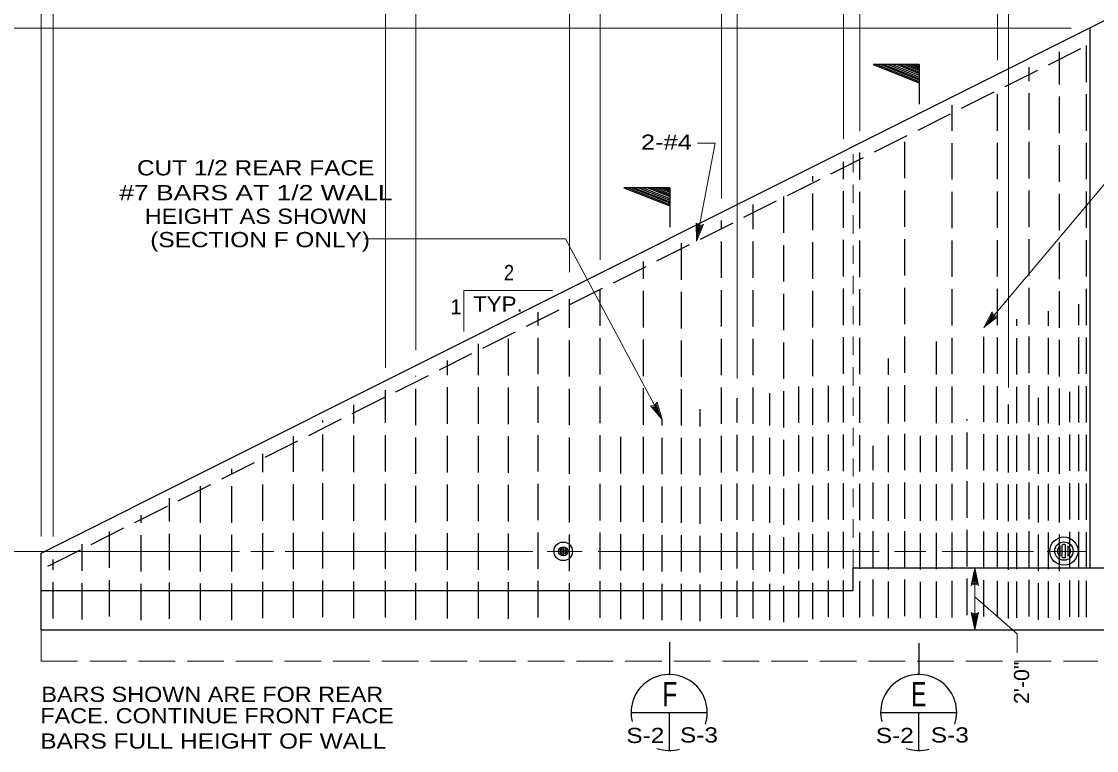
# Model space of a CAD drawing. Extents: x -22.3 to 19.7, y -11.8 to 18.2.
# Drawn here: x -17.19 to -8.36, y 7.76 to 13.75 of the extents above; entities that cross this region are included whole.
import ezdxf
from ezdxf.enums import TextEntityAlignment as Align

# ---------------------------------------------------------------- set-up
doc = ezdxf.new("R2010")
doc.units = 0
doc.header["$LTSCALE"] = 0.05
doc.linetypes.add('LONG_DASHED', pattern=[7.5, 6, -1.5])
doc.linetypes.add('MEDIUM_DASHED', pattern=[4.5, 3, -1.5])
doc.layers.add('1', color=7, linetype='Continuous', lineweight=13)
doc.layers.add('2', color=7, linetype='Continuous', lineweight=13)

msp = doc.modelspace()

# ---------------------------------------------------------------- linework, layer by layer
at = {"layer": '1'}
for p, q in [((-17.03142, 9.51631), (-17.03142, 15.50531)), ((-16.93242, 9.51631), (-16.93242, 15.50531)), ((-10.43842, 12.78231), (-10.43842, 15.50531)), ((-10.30342, 12.84831), (-10.30342, 15.50531)), ((-14.20242, 10.90131), (-14.20242, 14.77631)), ((-13.95142, 11.04731), (-13.95142, 14.77631)), ((-12.68842, 11.68931), (-12.68842, 14.77631)), ((-12.43842, 11.79131), (-12.43842, 14.77631)), ((-11.43942, 12.29431), (-11.43942, 14.77631)), ((-11.31242, 10.81431), (-11.31242, 14.77631)), ((-9.17242, 13.43131), (-9.17242, 14.77631)), ((-9.08142, 10.74131), (-9.08142, 14.77631)), ((-8.56742, 13.69631), (-18.54542, 13.69631)), ((-11.64642, 11.94431), (-11.64942, 12.09131)), ((-11.64642, 11.94431), (-11.58842, 12.08031)), ((-11.63942, 11.98031), (-11.64142, 12.07631)), ((-11.64142, 12.07631), (-11.62342, 12.06431)), ((-11.63942, 11.98031), (-11.60242, 12.06931)), ((-11.63242, 12.01631), (-11.63442, 12.06231)), ((-11.63442, 12.06231), (-11.62442, 12.05631)), ((-11.63242, 12.01631), (-11.61542, 12.05831)), ((-11.62442, 12.05631), (-11.61542, 12.05831)), ((-11.62342, 12.06431), (-11.60242, 12.06931)), ((-9.28542, 11.23331), (-9.21642, 11.36331)), ((-9.28542, 11.23331), (-9.16942, 11.32331)), ((-9.26142, 11.26131), (-9.21642, 11.34631)), ((-9.26142, 11.26131), (-9.18542, 11.32031)), ((-9.23842, 11.28931), (-9.21742, 11.33031)), ((-9.23842, 11.28931), (-9.20242, 11.31831)), ((-9.21742, 11.33031), (-9.21242, 11.32031)), ((-9.21642, 11.34631), (-9.20742, 11.32631)), ((-9.21242, 11.32031), (-9.20242, 11.31831)), ((-9.20742, 11.32631), (-9.18542, 11.32031)), ((-11.98642, 10.58531), (-11.97342, 10.60231)), ((-11.94642, 10.51031), (-11.97342, 10.60231)), ((-11.92942, 10.47731), (-11.96942, 10.61931)), ((-11.92942, 10.47731), (-12.02442, 10.58931)), ((-12.00842, 10.58331), (-11.98642, 10.58531)), ((-11.94642, 10.51031), (-12.00842, 10.58331)), ((-11.99342, 10.57631), (-11.98342, 10.57831)), ((-11.96342, 10.54131), (-11.99342, 10.57631)), ((-11.98342, 10.57831), (-11.97742, 10.58531)), ((-11.96342, 10.54131), (-11.97742, 10.58531)), ((-18.92042, 9.39231), (-15.40142, 9.39231)), ((-15.30742, 9.39231), (-15.11942, 9.39231)), ((-15.02542, 9.39231), (-12.99042, 9.39231)), ((-12.87342, 9.39231), (-12.58642, 9.39231)), ((-12.45542, 9.39231), (-10.14442, 9.39231)), ((-10.01842, 9.39231), (-9.76042, 9.39231)), ((-9.62742, 9.39231), (-8.87542, 9.39231)), ((-8.76542, 9.39231), (-8.44442, 9.39231)), ((-9.35842, 9.25831), (-9.38942, 9.11431)), ((-9.35842, 9.22131), (-9.37842, 9.12731)), ((-9.35842, 8.74831), (-9.35842, 9.25831)), ((-9.35842, 9.25831), (-9.32742, 9.11431)), ((-9.35842, 9.22131), (-9.33842, 9.12731)), ((-9.35842, 9.13631), (-9.37842, 9.12731)), ((-9.35842, 9.18531), (-9.36742, 9.14031)), ((-9.35842, 9.14431), (-9.36742, 9.14031)), ((-9.35842, 9.18531), (-9.34842, 9.14031)), ((-9.34842, 9.14031), (-9.35842, 9.14431)), ((-9.33842, 9.12731), (-9.35842, 9.13631)), ((-9.35842, 9.01931), (-9.00842, 8.71431)), ((-9.35842, 8.74831), (-9.38942, 8.89231)), ((-9.35842, 8.78531), (-9.37842, 8.87931)), ((-9.37842, 8.87931), (-9.35842, 8.87031)), ((-9.35842, 8.82131), (-9.36842, 8.86631)), ((-9.36842, 8.86631), (-9.35842, 8.86231)), ((-9.35842, 8.74831), (-9.32742, 8.89231)), ((-9.35842, 8.78531), (-9.33842, 8.87931)), ((-9.35842, 8.87031), (-9.33842, 8.87931)), ((-9.35842, 8.82131), (-9.34942, 8.86631)), ((-9.35842, 8.86231), (-9.34942, 8.86631)), ((-9.01042, 8.71431), (-9.01042, 8.56031))]:
    msp.add_line(p, q, dxfattribs=at)
at = {"layer": '1', "lineweight": 25}
for p, q in [((-8.41042, 9.25831), (-8.41042, 13.69631)), ((-12.76042, 9.37431), (-12.76042, 9.41631)), ((-12.74942, 9.36731), (-12.74942, 9.42131)), ((-12.73542, 9.36731), (-12.73542, 9.42131)), ((-12.72342, 9.37431), (-12.72342, 9.41631)), ((-8.65842, 9.35331), (-8.65842, 9.43831)), ((-8.64042, 9.34431), (-8.64042, 9.44831)), ((-8.61342, 9.34331), (-8.61342, 9.44831)), ((-8.59142, 9.35331), (-8.59142, 9.43831)), ((-17.03142, 8.74831), (1.83058, 8.74831))]:
    msp.add_line(p, q, dxfattribs=at)
at = {"layer": '1', "linetype": 'LONG_DASHED', "lineweight": 25}
for p, q in [((-16.97742, 9.27231), (-8.48842, 13.52731)), ((-8.44242, 8.85231), (-8.44242, 13.58331)), ((-8.66242, 8.83231), (-8.66242, 13.50031)), ((-8.91342, 8.85931), (-8.91342, 13.37331)), ((-9.17242, 8.85231), (-9.17242, 13.23131)), ((-9.54542, 8.85031), (-9.54542, 13.06331)), ((-9.93442, 8.86131), (-9.93442, 12.85431)), ((-10.30342, 8.84931), (-10.30342, 12.67231)), ((-10.43842, 8.85431), (-10.43842, 12.59731)), ((-10.69042, 8.83531), (-10.69042, 12.47931)), ((-10.92842, 8.81131), (-10.92842, 12.38131)), ((-11.18142, 8.84231), (-11.18142, 12.24631)), ((-11.43942, 8.84231), (-11.43942, 12.11331)), ((-11.76842, 8.82731), (-11.76842, 11.93831)), ((-12.08142, 8.83531), (-12.08142, 11.77731)), ((-12.43842, 8.84831), (-12.43842, 11.58931)), ((-12.68842, 8.83131), (-12.68842, 11.46631)), ((-8.50442, 8.85431), (-8.50442, 11.42531)), ((-12.94642, 8.85031), (-12.94642, 11.36131)), ((-8.75442, 8.84831), (-8.75442, 11.36731)), ((-9.28542, 8.85831), (-9.28542, 11.23331)), ((-9.01242, 8.84731), (-9.01242, 11.30331)), ((-13.19042, 8.84031), (-13.19042, 11.21631)), ((-13.43842, 8.84331), (-13.43842, 11.09931)), ((-9.67442, 8.84731), (-9.67442, 11.11931)), ((-13.69242, 8.84331), (-13.69242, 10.96331)), ((-10.06742, 8.84531), (-10.06742, 10.97931)), ((-13.95142, 8.83131), (-13.95142, 10.83631)), ((-10.80542, 8.85031), (-10.80542, 10.77831)), ((-10.56142, 8.85531), (-10.56142, 10.83331)), ((-14.20242, 8.85031), (-14.20242, 10.71931)), ((-11.04442, 8.82831), (-11.04442, 10.69531)), ((-8.57842, 8.85531), (-8.57842, 10.70431)), ((-11.31242, 8.85231), (-11.31242, 10.65231)), ((-9.08142, 8.84231), (-9.08142, 10.60231)), ((-8.83642, 8.83231), (-8.83642, 10.65531)), ((-14.46142, 8.84531), (-14.46142, 10.59831)), ((-11.61542, 8.82131), (-11.61542, 10.56231)), ((-14.71642, 8.85331), (-14.71642, 10.47331)), ((-11.92942, 8.82831), (-11.92942, 10.47731)), ((-9.42142, 8.87031), (-9.42142, 10.48131)), ((-14.95642, 8.84731), (-14.95642, 10.34031)), ((-12.26742, 8.83531), (-12.26742, 10.35931)), ((-9.80642, 8.84431), (-9.80642, 10.35631)), ((-10.19342, 8.86131), (-10.19342, 10.26231)), ((-15.21042, 8.84431), (-15.21042, 10.19531)), ((-15.46342, 8.82931), (-15.46342, 10.07131)), ((-15.72142, 8.82931), (-15.72142, 9.93131)), ((-15.97542, 8.83931), (-15.97542, 9.83031)), ((-16.20842, 8.82831), (-16.20842, 9.69031)), ((-16.47042, 8.85831), (-16.47042, 9.56531)), ((-16.69342, 8.83331), (-16.69342, 9.45331)), ((-16.93242, 8.84131), (-16.93242, 9.32831))]:
    msp.add_line(p, q, dxfattribs=at)
at = {"layer": '1', "linetype": 'MEDIUM_DASHED'}
msp.add_line((-10.35942, 9.25831), (-10.35942, 12.72331), dxfattribs=at)
at = {"layer": '1', "linetype": 'LONG_DASHED'}
for p, q in [((-17.03142, 8.74831), (-17.03142, 8.49031)), ((-17.03142, 8.49031), (-8.34742, 8.49031))]:
    msp.add_line(p, q, dxfattribs=at)
at = {"layer": '1'}
for points in [[(-9.28542, 11.23331), (-6.31842, 14.76331), (-5.93842, 14.76331)], [(-11.64642, 11.94431), (-11.49142, 12.75031), (-11.63742, 12.75031)], [(-11.64942, 12.09131), (-11.62142, 12.07231), (-11.58842, 12.08031)], [(-11.92942, 10.47731), (-12.72242, 11.96431), (-14.37142, 11.96431)], [(-13.55742, 11.20231), (-13.55742, 11.53931), (-12.82942, 11.53931)], [(-9.21642, 11.36331), (-9.20142, 11.33331), (-9.16942, 11.32331)], [(-12.02442, 10.58931), (-11.99042, 10.59231), (-11.96942, 10.61931)], [(-9.32742, 9.11431), (-9.35842, 9.12831), (-9.38942, 9.11431)], [(-9.38942, 8.89231), (-9.35842, 8.87831), (-9.32742, 8.89231)]]:
    msp.add_lwpolyline(points, dxfattribs=at)
at = {"layer": '1', "lineweight": 25}
for points in [[(-17.03142, 8.74831), (-17.03142, 9.37931), (-8.17942, 13.81631), (-1.11242, 13.81631), (1.83058, 12.34331)], [(-17.03142, 9.07131), (-10.35942, 9.07131), (-10.35942, 9.25831), (1.04358, 9.25831), (1.04358, 9.08631)]]:
    msp.add_lwpolyline(points, dxfattribs=at)
for centre, radius in [((-12.74142, 9.39431), 0.07624), ((-8.62642, 9.39631), 0.11574), ((-8.62642, 9.39631), 0.07571), ((-12.74142, 9.39431), 0.03821)]:
    msp.add_circle(centre, radius, dxfattribs=at)
for centre, radius, start, end in [((-12.74142, 9.39431), 0.02802, 130.60129, 226.4688), ((-12.74142, 9.39431), 0.02802, 251.56505, 282.09476), ((-12.74142, 9.39431), 0.02802, 77.47119, 106.50436), ((-12.74142, 9.39431), 0.02802, 310.60129, 50.71059), ((-8.62642, 9.39631), 0.05401, 126.02737, 233.1301), ((-8.62642, 9.39631), 0.05401, 75.96376, 104.03624), ((-8.62642, 9.39631), 0.05401, 309.80557, 48.81408), ((-8.62642, 9.39631), 0.05401, 254.93151, 282.75753)]:
    msp.add_arc(centre, radius, start, end, dxfattribs=at)
at = {"layer": '2', "lineweight": 25}
for p, q in [((-10.16342, 13.39531), (-9.81542, 13.25731)), ((-10.13042, 13.39531), (-9.81542, 13.27031)), ((-10.10742, 13.39531), (-9.81542, 13.27931)), ((-10.07142, 13.39531), (-9.81542, 13.29331)), ((-10.03742, 13.39531), (-9.81542, 13.30731)), ((-9.99642, 13.39531), (-9.81542, 13.32331)), ((-9.96942, 13.39531), (-9.81542, 13.33431)), ((-9.93742, 13.39531), (-9.81542, 13.34631)), ((-9.90842, 13.39531), (-9.81542, 13.35831)), ((-9.87942, 13.39531), (-9.81542, 13.36931)), ((-9.85942, 13.39531), (-9.81542, 13.37731)), ((-9.83242, 13.39531), (-9.81542, 13.38831)), ((-9.81542, 13.39531), (-9.81542, 13.07131)), ((-12.21342, 12.38331), (-11.86542, 12.24531)), ((-12.18042, 12.38331), (-11.86542, 12.25831)), ((-12.15742, 12.38331), (-11.86542, 12.26731)), ((-12.12142, 12.38331), (-11.86542, 12.28131)), ((-12.08742, 12.38331), (-11.86542, 12.29531)), ((-12.04642, 12.38331), (-11.86542, 12.31131)), ((-12.01942, 12.38331), (-11.86542, 12.32231)), ((-11.98742, 12.38331), (-11.86542, 12.33431)), ((-11.95842, 12.38331), (-11.86542, 12.34631)), ((-11.92942, 12.38331), (-11.86542, 12.35731)), ((-11.90942, 12.38331), (-11.86542, 12.36531)), ((-11.88242, 12.38331), (-11.86542, 12.37631)), ((-11.86542, 12.38331), (-11.86542, 12.05931)), ((-11.86542, 8.38331), (-11.86542, 8.64831)), ((-9.81542, 8.38331), (-9.81542, 8.63931)), ((-12.18242, 8.06931), (-11.55842, 8.06931)), ((-11.87042, 8.06931), (-11.87042, 7.75731)), ((-10.13242, 8.06931), (-9.50842, 8.06931)), ((-9.82042, 8.06931), (-9.82042, 7.75731))]:
    msp.add_line(p, q, dxfattribs=at)
for points in [[(-9.81542, 13.39531), (-10.19442, 13.39531), (-9.81542, 13.24531)], [(-11.86542, 12.38331), (-12.24442, 12.38331), (-11.86542, 12.23331)]]:
    msp.add_lwpolyline(points, dxfattribs=at)
for centre, start, end in [((-11.87042, 8.06931), 341.96976, 193.81208), ((-9.82042, 8.06931), 341.96976, 193.81208), ((-11.87042, 8.06931), 251.04049, 285.74671), ((-9.82042, 8.06931), 251.04049, 285.74671)]:
    msp.add_arc(centre, 0.3125, start, end, dxfattribs=at)

# ---------------------------------------------------------------- texts
at = {"layer": '1'}
for s, width, p in [('2-#4', 1.25, (-11.68442, 12.69531)), ('(SECTION F ONLY)', 1.2, (-14.32942, 11.89431))]:
    msp.add_text(s, height=0.125, dxfattribs=dict(at, width=width)).set_placement(p, align=Align.RIGHT)
for s, width, p in [('CUT 1/2 REAR FACE', 1.2, (-15.26892, 12.48431)), ('#7 BARS AT 1/2 WALL', 1.3, (-15.26592, 12.28031)), ('HEIGHT AS SHOWN', 1.15, (-15.26692, 12.08631)), ('2', 0.9, (-13.18692, 11.62331)), ('TYP.', 1.1, (-13.27792, 11.36431))]:
    msp.add_text(s, height=0.125, dxfattribs=dict(at, width=width)).set_placement(p, align=Align.CENTER)
msp.add_text('1', height=0.125, dxfattribs=at).set_placement((-13.62253, 11.34131), align=Align.CENTER)
at = {"layer": '1', "width": 1.05}
msp.add_text('2\'-0"', height=0.125, rotation=90, dxfattribs=at).set_placement((-8.91242, 8.48831), align=Align.RIGHT)
at = {"layer": '1'}
for s, width, p in [('BARS SHOWN ARE FOR REAR', 1.15, (-17.02942, 8.15631)), ('FACE. CONTINUE FRONT FACE', 1.15, (-17.03842, 7.98031)), ('BARS FULL HEIGHT OF WALL', 1.2, (-17.03842, 7.77231))]:
    msp.add_text(s, height=0.125, dxfattribs=dict(at, width=width)).set_placement(p)
at = {"layer": '2'}
for s, height, width, p in [('F', 0.2, 0.75, (-11.86542, 8.12031)), ('E', 0.2, 0.7, (-9.81942, 8.12031)), ('S-2', 0.125, 1.2, (-12.06642, 7.81831)), ('S-3', 0.125, 1.2, (-11.62542, 7.82231)), ('S-2', 0.125, 1.2, (-10.01642, 7.81831)), ('S-3', 0.125, 1.2, (-9.56442, 7.82231))]:
    msp.add_text(s, height=height, dxfattribs=dict(at, width=width)).set_placement(p, align=Align.CENTER)

doc.saveas('drawing.dxf')
